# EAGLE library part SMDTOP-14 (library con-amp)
AMP connector
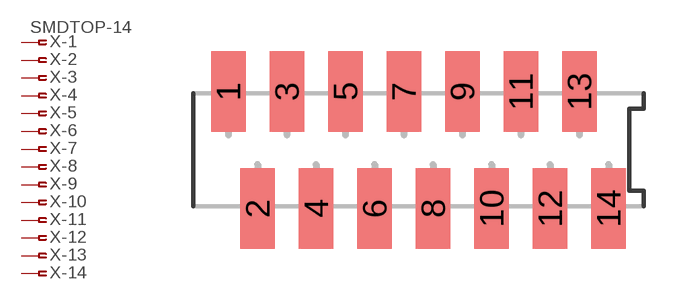
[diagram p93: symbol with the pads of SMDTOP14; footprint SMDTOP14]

Designator prefix X; gates -1=PIN-FV -2=PIN-F -3=PIN-F -4=PIN-F -5=PIN-F -6=PIN-F -7=PIN-F -8=PIN-F -9=PIN-F -10=PIN-F -11=PIN-F -12=PIN-F -13=PIN-F -14=PIN-F

## SMDTOP-14 (OC_FARNELL: unknown; OC_NEWARK: unknown)  [SMDTOP14]
1  -1:1  pas
2  -2:1  pas
3  -3:1  pas
4  -4:1  pas
5  -5:1  pas
6  -6:1  pas
7  -7:1  pas
8  -8:1  pas
9  -9:1  pas
10  -10:1  pas
11  -11:1  pas
12  -12:1  pas
13  -13:1  pas
14  -14:1  pas

## Footprint SMDTOP14 (pad centres in mm)
AMP connector
smd 1.5 x 3.5: 1 -8.255,2.54; 2 -6.985,-2.54; 3 -5.715,2.54; 4 -4.445,-2.54; 5 -3.175,2.54; 6 -1.905,-2.54; 7 -0.635,2.54; 8 0.635,-2.54; 9 1.905,2.54; 10 3.175,-2.54; 11 4.445,2.54; 12 5.715,-2.54; 13 6.985,2.54; 14 8.255,-2.54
